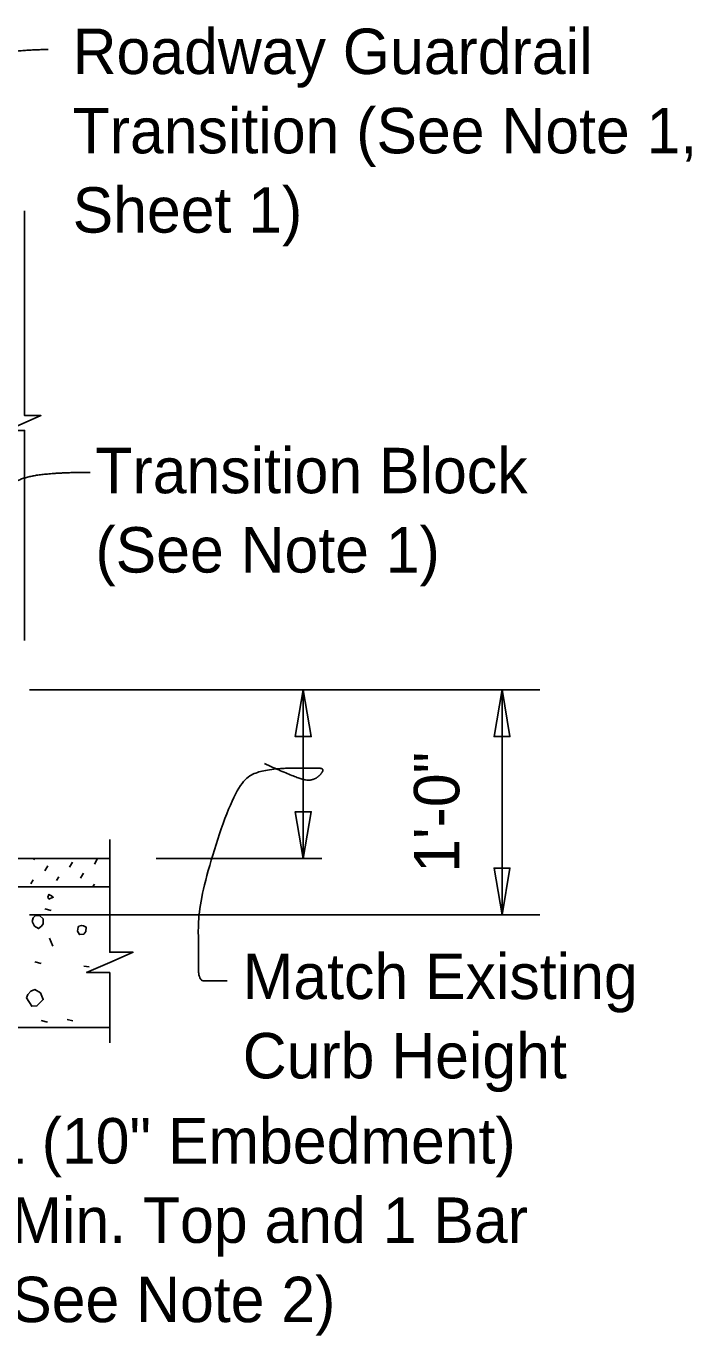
# Model space of a CAD drawing. Extents: x 21587 to 21656.3, y 56117.4 to 56157.3.
# Drawn here: x 21623.99 to 21626.94, y 56131.93 to 56137.75 of the extents above; entities that cross this region are included whole.
import ezdxf

# ---------------------------------------------------------------- set-up
doc = ezdxf.new("R2010")
doc.units = 0
for name, color, linetype in [('AdhocPoint_dp', 7, 'Continuous'), ('PlotBorder_dp', 7, 'Continuous'), ('SheetBorder_dp', 7, 'Continuous'), ('TextMisc', 7, 'Continuous')]:
    doc.layers.add(name, color=color, linetype=linetype)

msp = doc.modelspace()

# ---------------------------------------------------------------- linework, layer by layer
at = {"layer": 'AdhocPoint_dp'}
for p, q in [((21624.3563, 56134.0511), (21613.608, 56134.0511)), ((21613.608, 56133.926), (21624.3563, 56133.926)), ((21624.3563, 56133.301), (21618.8279, 56133.301))]:
    msp.add_line(p, q, dxfattribs=at)
at = {"layer": 'PlotBorder_dp'}
for p, q in [((21623.9999, 56134.8009), (21626.2654, 56134.8009)), ((21625.2148, 56134.8009), (21625.2148, 56134.0509)), ((21626.0969, 56134.801), (21626.0969, 56133.801)), ((21624.5621, 56134.0509), (21625.2975, 56134.0509)), ((21623.9999, 56133.8009), (21626.2654, 56133.8009))]:
    msp.add_line(p, q, dxfattribs=at)
for points in [[(21623.978, 56135.0198), (21623.978, 56135.9514), (21623.9005, 56135.9514), (21624.0505, 56136.0177), (21623.978, 56136.0177), (21623.978, 56136.9265)], [(21624.3563, 56133.233), (21624.3563, 56133.5455), (21624.253, 56133.5455), (21624.3563, 56133.5905), (21624.4596, 56133.6355), (21624.3563, 56133.6355), (21624.3563, 56134.1353)]]:
    msp.add_lwpolyline(points, dxfattribs=at)
for points in [[(21625.2148, 56134.8009), (21625.1795, 56134.5927), (21625.2501, 56134.5927)], [(21626.0969, 56134.801), (21626.0616, 56134.5928), (21626.1322, 56134.5928)], [(21625.2148, 56134.0509), (21625.2501, 56134.2592), (21625.1795, 56134.2592)], [(21626.0969, 56133.801), (21626.1322, 56134.0093), (21626.0616, 56134.0093)]]:
    msp.add_lwpolyline(points, close=True, dxfattribs=at)
for points in [[(21624.0822, 56137.6421), (21623.8314, 56137.6421), (21623.38, 56137.4716), (21622.9637, 56137.256), (21622.4973, 56136.7845)], [(21624.2687, 56135.7655), (21624.0532, 56135.7655), (21623.8906, 56135.7125), (21623.6609, 56135.412), (21623.4241, 56134.8039)], [(21624.8766, 56133.5082), (21624.7988, 56133.5082), (21624.7493, 56133.5082), (21624.7493, 56133.6284), (21624.7493, 56133.8724), (21624.919, 56134.3956), (21625.0533, 56134.4522), (21625.2547, 56134.4522), (21625.3148, 56134.4522), (21625.2688, 56134.3991), (21625.2017, 56134.3991), (21625.0427, 56134.4734)]]:
    msp.add_open_spline(points, degree=2, dxfattribs=at)
at = {"layer": 'TextMisc'}
for p, q in [((21624.0189, 56134.0456), (21624.022, 56134.0511)), ((21624.2877, 56134.0266), (21624.3007, 56134.049)), ((21624.0677, 56133.9968), (21624.0807, 56134.0192)), ((21624.1771, 56134.0136), (21624.19, 56134.036)), ((21624.2259, 56133.9648), (21624.2389, 56133.9872)), ((21624.0058, 56133.9392), (21624.0157, 56133.9563)), ((21624.1196, 56133.9533), (21624.1295, 56133.9704)), ((21624.2796, 56133.9243), (21624.2877, 56133.9383)), ((21624.1764, 56133.9243), (21624.1771, 56133.9254)), ((21624.0678, 56133.8276), (21624.0961, 56133.8206)), ((21624.1027, 56133.6624), (21624.0886, 56133.6978)), ((21624.0232, 56133.5932), (21624.0515, 56133.5862)), ((21624.2406, 56133.574), (21624.2653, 56133.5705)), ((21624.0513, 56133.3324), (21624.0796, 56133.3254)), ((21624.1663, 56133.3371), (21624.1928, 56133.3318))]:
    msp.add_line(p, q, dxfattribs=at)
for points in [[(21624.0858, 56133.8707), (21624.1052, 56133.8796), (21624.0982, 56133.8866), (21624.0858, 56133.8919), (21624.0805, 56133.8796), (21624.0858, 56133.8707)], [(21624.011, 56133.7727), (21624.0216, 56133.7515), (21624.0393, 56133.7409), (21624.0534, 56133.7515), (21624.0605, 56133.7621), (21624.0605, 56133.7833), (21624.0446, 56133.7993), (21624.0251, 56133.7975), (21624.0163, 56133.7886), (21624.011, 56133.7727)], [(21624.2123, 56133.7296), (21624.2211, 56133.7137), (21624.2406, 56133.7155), (21624.2494, 56133.7278), (21624.2512, 56133.7473), (21624.2388, 56133.7526), (21624.23, 56133.7543), (21624.2194, 56133.7508), (21624.2158, 56133.7473), (21624.2123, 56133.7296)], [(21623.9865, 56133.4326), (21624.0095, 56133.3955), (21624.0325, 56133.3972), (21624.0413, 56133.4061), (21624.0607, 56133.4255), (21624.0484, 56133.4556), (21624.0236, 56133.4697), (21624.0059, 56133.4627), (21623.9918, 56133.4485), (21623.9865, 56133.4326)]]:
    msp.add_lwpolyline(points, dxfattribs=at)

# ---------------------------------------------------------------- texts
at = {"layer": 'PlotBorder_dp'}
for s, p in [('Roadway Guardrail ', (21624.1914, 56137.5335)), ('Transition (See Note 1, ', (21624.1914, 56137.1815)), ('Sheet 1)', (21624.1914, 56136.8295)), ('Transition Block', (21624.2925, 56135.6728)), ('(See Note 1)', (21624.2925, 56135.3208)), ('Match Existing ', (21624.9463, 56133.4277)), ('Curb Height', (21624.9463, 56133.0757)), ('Dowel Bars 4L (10" Embedment) ', (21622.226, 56132.6977)), ('(Place 3 Bars Min. Top and 1 Bar ', (21622.226, 56132.3457)), ('Min. Bottom) (See Note 2)', (21622.226, 56131.9937))]:
    msp.add_text(s, height=0.2016, dxfattribs=at).set_placement(p)
at = {"layer": 'SheetBorder_dp'}
msp.add_text('1\'-0"', height=0.2016, rotation=90, dxfattribs=at).set_placement((21625.9073, 56133.9882))

doc.saveas('drawing.dxf')
